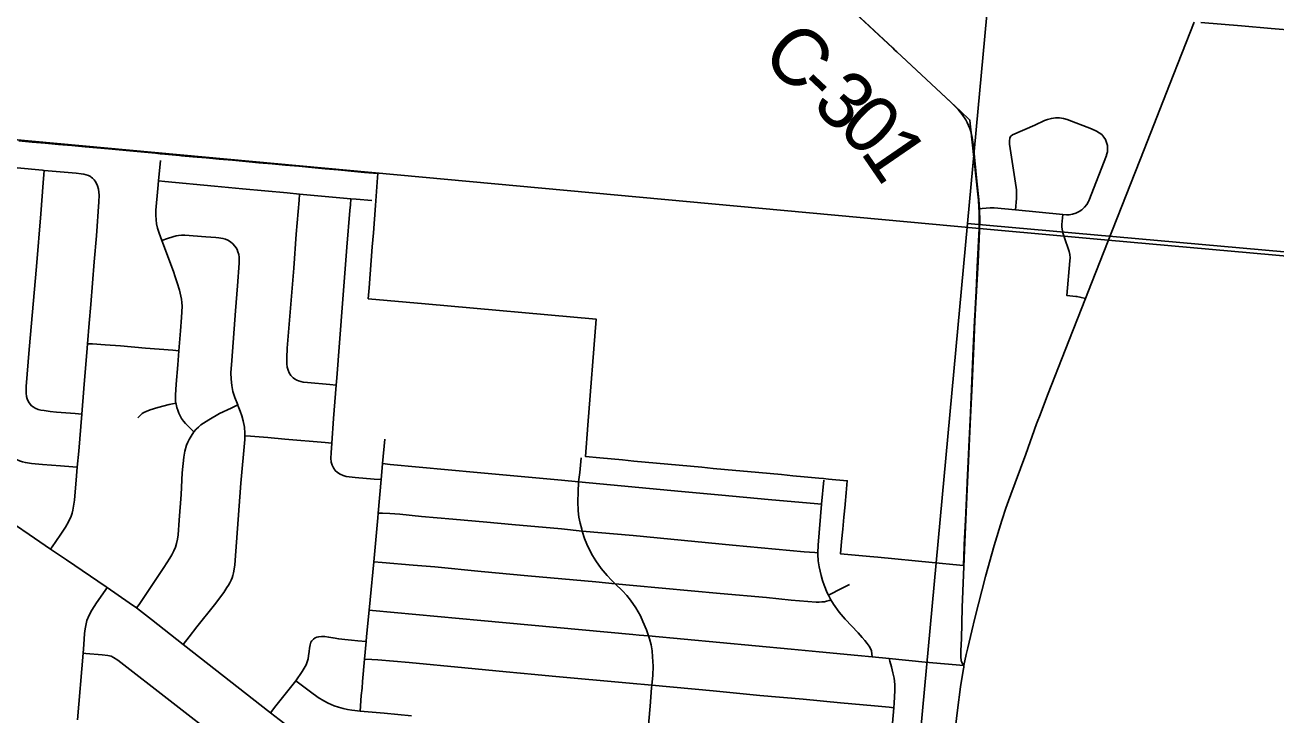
# Model space of a CAD drawing. Extents: x 0 to 1134, y 0 to 440.
# Drawn here: x 834.996 to 836.243, y 364.489 to 365.176 of the extents above; entities that cross this region are included whole.
import ezdxf

# ---------------------------------------------------------------- set-up
doc = ezdxf.new("R2010")
doc.units = 0
for name, color, linetype in [('GM_X_City_Street', 7, 'Continuous'), ('GM_X_Corporation', 7, 'Continuous'), ('GM_X_County_Road', 7, 'Continuous'), ('GM_X_County_Road_Text', 7, 'Continuous'), ('GM_X_Section', 7, 'Continuous'), ('GM_X_State_Route', 7, 'Continuous'), ('GM_X_Township', 7, 'Continuous'), ('GM_X_Township_Road', 7, 'Continuous'), ('GM_X_Unincorporated', 7, 'Continuous')]:
    doc.layers.add(name, color=color, linetype=linetype)

msp = doc.modelspace()

# ---------------------------------------------------------------- linework, layer by layer
at = {"layer": 'GM_X_City_Street'}
for points in [[(834.9536, 365.0365), (834.9603, 365.0361), (834.9634, 365.0359), (834.9883, 365.0336), (835.0133, 365.0314), (835.0149, 365.0312), (835.0469, 365.0284), (835.052, 365.0278), (835.0546, 365.0274), (835.057, 365.0268), (835.0591, 365.026), (835.0612, 365.0249), (835.0619, 365.0245)], [(835.0525, 364.7884), (835.046, 364.7889), (835.0272, 364.7904), (835.0209, 364.7911), (835.015, 364.7919), (835.0119, 364.7924), (835.0092, 364.793), (835.0062, 364.7942), (835.0041, 364.7955), (835.0026, 364.7967), (835.0012, 364.7981), (834.9995, 364.8007), (834.9981, 364.8035), (834.9975, 364.806), (834.997, 364.8092), (834.9971, 364.8157), (835.0002, 364.8526), (835.0075, 364.9355), (835.0117, 364.9878), (835.0139, 365.0186), (835.0146, 365.0272), (835.0149, 365.0312)], [(835.1644, 364.7708), (835.1605, 364.7744), (835.156, 364.779), (835.1539, 364.7813), (835.1521, 364.7839), (835.1506, 364.7865), (835.1493, 364.7893), (835.1482, 364.7922), (835.1473, 364.7951), (835.1465, 364.7981), (835.1464, 364.7992), (835.1461, 364.8012), (835.1459, 364.8043), (835.146, 364.8073), (835.1467, 364.8183), (835.1483, 364.8375), (835.1494, 364.8514), (835.1509, 364.8713), (835.152, 364.8845), (835.1525, 364.8959), (835.1523, 364.8997), (835.1519, 364.903), (835.1514, 364.906), (835.1499, 364.9118), (835.1477, 364.9191), (835.1457, 364.9251), (835.144, 364.9303), (835.1325, 364.9612), (835.1297, 364.9685), (835.128, 364.9737), (835.127, 364.9779), (835.1266, 364.982), (835.1264, 364.9864), (835.1265, 364.9914), (835.1284, 365.013), (835.129, 365.0206), (835.131, 365.0411)], [(835.0215, 364.6538), (835.0261, 364.6606), (835.0323, 364.6696), (835.0363, 364.6757), (835.0394, 364.6811), (835.0419, 364.6868), (835.0429, 364.6897), (835.0437, 364.6927), (835.0444, 364.6968), (835.0452, 364.7027), (835.0473, 364.7268), (835.0481, 364.7354), (835.0495, 364.7516), (835.0525, 364.7884), (835.0545, 364.8138), (835.0578, 364.8542), (835.0581, 364.8585), (835.0599, 364.879), (835.0615, 364.8976), (835.065, 364.9399), (835.0671, 364.9659), (835.0696, 364.9999), (835.0699, 365.0064), (835.0696, 365.0095), (835.0691, 365.0125), (835.0682, 365.0157), (835.0669, 365.0187), (835.0658, 365.0204), (835.0648, 365.0218), (835.0634, 365.0233), (835.0619, 365.0245)], [(835.129, 365.0206), (835.1353, 365.0201), (835.1848, 365.0155), (835.2127, 365.0129), (835.2574, 365.0087), (835.2696, 365.0076), (835.3208, 365.0029), (835.3261, 365.0024), (835.3416, 365.001)], [(835.3061, 364.8173), (835.2997, 364.8178), (835.2775, 364.8197), (835.2732, 364.8202), (835.2708, 364.8208), (835.2686, 364.8215), (835.2668, 364.8222), (835.2647, 364.8234), (835.2632, 364.8245), (835.2611, 364.8268), (835.2594, 364.8294), (835.2582, 364.8322), (835.2573, 364.8351), (835.2568, 364.8385), (835.2568, 364.841), (835.2568, 364.8444), (835.2574, 364.8539), (835.2594, 364.8779), (835.264, 364.9336), (835.2664, 364.9675), (835.2691, 365.0014), (835.2696, 365.0076)], [(835.351, 364.7231), (835.3439, 364.7237), (835.3252, 364.7251), (835.3191, 364.7258), (835.316, 364.7263), (835.313, 364.7271), (835.3102, 364.7284), (835.3076, 364.7301), (835.3053, 364.7323), (835.3034, 364.7347), (835.302, 364.7375), (835.3011, 364.7406), (835.3007, 364.7444), (835.301, 364.7498), (835.3017, 364.7594), (835.3035, 364.7839), (835.3061, 364.8173), (835.3067, 364.8246), (835.3125, 364.8986), (835.3167, 364.9545), (835.3199, 364.9913), (835.3203, 364.997), (835.3208, 365.0029)], [(835.1537, 364.559), (835.1596, 364.5666), (835.1672, 364.5764), (835.1847, 364.5982), (835.1941, 364.6106), (835.1973, 364.6156), (835.1989, 364.6179), (835.2002, 364.6203), (835.2015, 364.623), (835.2024, 364.6254), (835.2032, 364.6276), (835.2039, 364.6303), (835.2046, 364.634), (835.205, 364.6381), (835.2111, 364.7195), (835.2152, 364.7631), (835.2152, 364.7666), (835.2152, 364.7693), (835.2147, 364.7755), (835.2136, 364.7816), (835.2121, 364.7867), (835.2104, 364.7914), (835.2085, 364.7963), (835.208, 364.7975), (835.2051, 364.805), (835.2033, 364.8109), (835.202, 364.817), (835.2014, 364.8232), (835.2013, 364.8294), (835.202, 364.8418), (835.2058, 364.8914), (835.2077, 364.9163), (835.2093, 364.9388), (835.2095, 364.9419), (835.2095, 364.9447), (835.2092, 364.9472), (835.2082, 364.9501), (835.2073, 364.9523), (835.2063, 364.9541), (835.2052, 364.9556), (835.2033, 364.958), (835.2009, 364.96), (835.1983, 364.9616), (835.1958, 364.9626), (835.1932, 364.9633), (835.1893, 364.9639), (835.1861, 364.9642), (835.1761, 364.965), (835.1552, 364.9666), (835.1521, 364.9665), (835.149, 364.9662), (835.1465, 364.9658), (835.1432, 364.965), (835.138, 364.9633), (835.1325, 364.9612)], [(835.0581, 364.8585), (835.0633, 364.8582), (835.076, 364.8574), (835.0913, 364.8563), (835.116, 364.8542), (835.1433, 364.8519), (835.1494, 364.8514)], [(835.1071, 364.5953), (835.1098, 364.5986), (835.1216, 364.6165), (835.1343, 364.6354), (835.1403, 364.6447), (835.1423, 364.6481), (835.1443, 364.652), (835.1459, 364.6559), (835.1471, 364.6596), (835.1481, 364.6639), (835.1487, 364.6682), (835.1498, 364.6827), (835.1516, 364.7084), (835.1526, 364.73), (835.1543, 364.7454), (835.1554, 364.7515), (835.1571, 364.7575), (835.1583, 364.7604), (835.1597, 364.7631), (835.1616, 364.7664), (835.1644, 364.7708), (835.1666, 364.7733), (835.169, 364.7755), (835.1713, 364.7776), (835.1738, 364.7794), (835.1791, 364.7828), (835.19, 364.7888), (835.2016, 364.7944), (835.208, 364.7975)], [(835.1086, 364.7847), (835.1108, 364.787), (835.1128, 364.7888), (835.1144, 364.79), (835.1166, 364.7911), (835.1207, 364.7927), (835.1283, 364.795), (835.1398, 364.7978), (835.1464, 364.7992)], [(834.9302, 364.7811), (834.936, 364.7774), (834.9464, 364.7706), (834.9693, 364.7548), (834.9849, 364.7447), (834.9876, 364.7432), (834.9904, 364.7418), (834.9933, 364.7408), (834.9963, 364.74), (835.0024, 364.7391), (835.0133, 364.7381), (835.0312, 364.7367), (835.0435, 364.7357), (835.0481, 364.7354)], [(835.2152, 364.7666), (835.2208, 364.7663), (835.2381, 364.7649), (835.2549, 364.7635), (835.2951, 364.76), (835.3017, 364.7594)], [(835.3302, 364.4925), (835.3312, 364.508), (835.3319, 364.5155), (835.3325, 364.5221), (835.3345, 364.5443), (835.336, 364.5617), (835.3365, 364.5668), (835.3391, 364.593), (835.34, 364.6032), (835.3437, 364.6411), (835.3476, 364.685), (835.348, 364.6897), (835.351, 364.7231), (835.352, 364.7347), (835.3524, 364.739), (835.3546, 364.7635)], [(835.616, 364.4637), (835.619, 364.4973), (835.6206, 364.5158), (835.6209, 364.5183), (835.6218, 364.5281), (835.6221, 364.5373), (835.6216, 364.5465), (835.621, 364.5526), (835.62, 364.5586), (835.6184, 364.5646), (835.6175, 364.5674), (835.6155, 364.5733), (835.612, 364.5819), (835.6094, 364.5874), (835.6048, 364.5954), (835.5997, 364.603), (835.5958, 364.6078), (835.5917, 364.6123), (835.5844, 364.6193), (835.5805, 364.623), (835.5762, 364.6275), (835.5702, 364.6347), (835.5649, 364.6423), (835.5616, 364.6476), (835.5586, 364.6531), (835.5559, 364.6588), (835.5537, 364.6646), (835.5515, 364.6718), (835.5509, 364.6736), (835.5494, 364.6796), (835.5482, 364.6858), (835.5475, 364.692), (835.5471, 364.7013), (835.5474, 364.7107), (835.5478, 364.721), (835.5489, 364.7302), (835.5505, 364.7447)], [(835.3524, 364.739), (835.3601, 364.7383), (835.4466, 364.7303), (835.5051, 364.725), (835.5309, 364.7226), (835.5478, 364.721), (835.6503, 364.7114), (835.6905, 364.7076), (835.7368, 364.7033), (835.7864, 364.6991), (835.7901, 364.6988)], [(835.8405, 364.5465), (835.8401, 364.5495), (835.8397, 364.5524), (835.8389, 364.5547), (835.8375, 364.5572), (835.8356, 364.5598), (835.833, 364.5627), (835.8304, 364.5658), (835.8264, 364.5705), (835.8136, 364.5841), (835.8076, 364.5912), (835.802, 364.599), (835.7994, 364.6034), (835.7986, 364.6048), (835.7969, 364.6079), (835.7956, 364.6102), (835.7925, 364.6181), (835.7909, 364.6227), (835.7896, 364.6275), (835.7877, 364.6361), (835.7867, 364.6422), (835.7862, 364.6484), (835.7863, 364.6501), (835.7866, 364.6577), (835.7901, 364.6988), (835.7922, 364.7226)], [(835.348, 364.6897), (835.3522, 364.6897), (835.3596, 364.6894), (835.3696, 364.6886), (835.3913, 364.6863), (835.4223, 364.6837), (835.4564, 364.6806), (835.4812, 364.6783), (835.5308, 364.6739), (835.5515, 364.6718), (835.6021, 364.6673), (835.7013, 364.6578), (835.7726, 364.6513), (835.7832, 364.6504), (835.7863, 364.6501)], [(835.3437, 364.6411), (835.3519, 364.6406), (835.3828, 364.638), (835.4044, 364.6361), (835.4508, 364.6315), (835.4971, 364.6273), (835.5651, 364.6211), (835.5844, 364.6193), (835.6022, 364.6176), (835.6888, 364.6098), (835.7351, 364.6055), (835.7598, 364.6031), (835.7846, 364.6011), (835.7876, 364.601), (835.7903, 364.6012), (835.7929, 364.6015), (835.7951, 364.602), (835.7975, 364.6028), (835.7994, 364.6034)], [(835.7969, 364.6079), (835.8003, 364.6097), (835.8071, 364.6133), (835.818, 364.6186)], [(835.0484, 364.4838), (835.0539, 364.5502), (835.0546, 364.5589), (835.0554, 364.5697), (835.0559, 364.5744), (835.0565, 364.5778), (835.0577, 364.5829), (835.06, 364.5882), (835.0626, 364.593), (835.0671, 364.6002), (835.0758, 364.6125), (835.0779, 364.6155)], [(835.3391, 364.593), (835.3425, 364.5927), (835.4505, 364.5829), (835.602, 364.5688), (835.6082, 364.5682), (835.6175, 364.5674), (835.7598, 364.5542), (835.7875, 364.5516), (835.8263, 364.5479), (835.8405, 364.5465), (835.8574, 364.5449), (835.8933, 364.5414)], [(835.2853, 364.5656), (835.2836, 364.5643), (835.282, 364.5626), (835.281, 364.561), (835.2801, 364.5585), (835.2795, 364.5552), (835.2791, 364.5519), (835.2786, 364.5474), (835.2781, 364.5447), (835.2773, 364.5416), (835.2762, 364.5387), (835.2744, 364.5352), (835.2723, 364.5318), (835.2658, 364.5228)], [(835.2853, 364.5656), (835.287, 364.5662), (835.2887, 364.5666), (835.2916, 364.5669), (835.295, 364.5668), (835.2986, 364.5662), (835.303, 364.5654), (835.3087, 364.5644), (835.3148, 364.5637), (835.3214, 364.563), (835.3278, 364.5625), (835.336, 364.5617)], [(835.1927, 364.4621), (835.0884, 364.5431), (835.0843, 364.5459), (835.0817, 364.5471), (835.0784, 364.5479), (835.073, 364.5487), (835.0567, 364.55), (835.0539, 364.5502)], [(835.3345, 364.5443), (835.3416, 364.5439), (835.3478, 364.5435), (835.3788, 364.5408), (835.4345, 364.5357), (835.4755, 364.5317), (835.5043, 364.529), (835.5215, 364.5274), (835.5984, 364.5203), (835.6209, 364.5183), (835.682, 364.5126), (835.7284, 364.5081), (835.7718, 364.5045), (835.8089, 364.5008), (835.8429, 364.4977), (835.8574, 364.4964), (835.8621, 364.4959)], [(835.8583, 364.454), (835.8621, 364.4959), (835.8625, 364.5005), (835.8632, 364.5129), (835.8631, 364.5191), (835.8624, 364.5252), (835.8612, 364.5307), (835.8597, 364.5366), (835.8581, 364.5421), (835.8574, 364.5449)], [(835.2658, 364.5228), (835.2461, 364.4977), (835.2407, 364.4908)], [(835.2658, 364.5228), (835.2806, 364.5118), (835.2883, 364.5062), (835.2937, 364.5028), (835.2982, 364.5003), (835.3043, 364.4977), (835.3084, 364.4964), (835.313, 364.4951), (835.3176, 364.4941), (835.3219, 364.4934), (835.3246, 364.4931), (835.3274, 364.4928), (835.3302, 364.4925)], [(835.3302, 364.4925), (835.3539, 364.4903), (835.3814, 364.4877)]]:
    msp.add_lwpolyline(points, dxfattribs=at)
at = {"layer": 'GM_X_Corporation'}
for points in [[(834.9898, 365.0606), (835.003, 365.0594), (835.0162, 365.0582), (835.0294, 365.057), (835.0426, 365.0558), (835.0558, 365.0546), (835.0791, 365.0525), (835.1006, 365.0505), (835.1261, 365.0482), (835.1308, 365.0478), (835.1355, 365.0473), (835.15, 365.046), (835.152, 365.0458), (835.1632, 365.0448), (835.1764, 365.0436), (835.1896, 365.0424), (835.2028, 365.0412), (835.216, 365.04), (835.2292, 365.0388), (835.2424, 365.0376), (835.2556, 365.0364), (835.2688, 365.0352), (835.282, 365.0339), (835.2952, 365.0327), (835.308, 365.0316), (835.3212, 365.0304), (835.3344, 365.0292), (835.3478, 365.0279), (835.3475, 365.0241), (835.3461, 365.0056), (835.3457, 365.0009), (835.3453, 364.9961), (835.3443, 364.9825), (835.3432, 364.9688), (835.3421, 364.9551), (835.3411, 364.9414), (835.34, 364.9278), (835.3389, 364.9141), (835.3381, 364.9033), (835.3949, 364.8982), (835.5654, 364.8829), (835.5571, 364.7773), (835.5548, 364.7461), (835.569, 364.7448), (835.5803, 364.7437), (835.5916, 364.7427), (835.6029, 364.7416), (835.6142, 364.7406), (835.6255, 364.7396), (835.6369, 364.7385), (835.6482, 364.7375), (835.6595, 364.7364), (835.6708, 364.7354), (835.6821, 364.7343), (835.6934, 364.7333), (835.7047, 364.7322), (835.7161, 364.7312), (835.7274, 364.7302), (835.7387, 364.7291), (835.75, 364.7281), (835.7613, 364.727), (835.7726, 364.726), (835.7874, 364.7246), (835.7921, 364.7242), (835.7968, 364.7237), (835.8156, 364.722), (835.8145, 364.7099), (835.8135, 364.6988), (835.8134, 364.6979), (835.8122, 364.6858), (835.8111, 364.6737), (835.8099, 364.6614), (835.8088, 364.6493), (835.8381, 364.6465), (835.8462, 364.6457), (835.9003, 364.6405), (835.9278, 364.6379), (835.9315, 364.6375), (835.9322, 364.6566), (835.9323, 364.6581), (835.9338, 364.6893), (835.9338, 364.6905), (835.9349, 364.7123), (835.9356, 364.7278), (835.9362, 364.7413), (835.9372, 364.7628), (835.9384, 364.7892), (835.9413, 364.854), (835.9426, 364.8816), (835.9431, 364.8918), (835.9432, 364.8933), (835.944, 364.9112), (835.944, 364.9112), (835.9451, 364.935), (835.947, 364.9732), (835.9471, 364.9776), (835.9471, 364.9778), (835.9471, 364.978), (835.9471, 364.9782), (835.9471, 364.9784), (835.9471, 364.9786), (835.9471, 364.9787), (835.9471, 364.9789), (835.9471, 364.9791), (835.9471, 364.9793), (835.9471, 364.9795), (835.9471, 364.9797), (835.9471, 364.9799), (835.9471, 364.98), (835.9471, 364.9802), (835.9471, 364.9804), (835.9471, 364.9806), (835.9471, 364.9808), (835.9471, 364.981), (835.9471, 364.9812), (835.9471, 364.9813), (835.9471, 364.9815), (835.9471, 364.9817), (835.9471, 364.9819), (835.9471, 364.9821), (835.9471, 364.9823), (835.9471, 364.9824), (835.9471, 364.9826), (835.9471, 364.9828), (835.9471, 364.983), (835.9471, 364.9832), (835.9471, 364.9834), (835.9471, 364.9836), (835.9471, 364.9837), (835.9471, 364.9839), (835.9471, 364.9841), (835.9471, 364.9843), (835.9471, 364.9845), (835.9471, 364.9847), (835.9471, 364.9849), (835.9471, 364.985), (835.9471, 364.9852), (835.9471, 364.9854), (835.9471, 364.9856), (835.9471, 364.9858), (835.9471, 364.986), (835.9471, 364.9862), (835.9471, 364.9863), (835.9471, 364.9865), (835.9471, 364.9867), (835.9471, 364.9869), (835.9471, 364.9871), (835.9471, 364.9873), (835.9471, 364.9875), (835.9471, 364.9876), (835.9471, 364.9878), (835.9471, 364.988), (835.9471, 364.9882), (835.9471, 364.9884), (835.9471, 364.9886), (835.9471, 364.9888), (835.9471, 364.9889), (835.947, 364.9891), (835.947, 364.9893), (835.947, 364.9895), (835.947, 364.9897), (835.947, 364.9899), (835.947, 364.99), (835.947, 364.9902), (835.947, 364.9904), (835.947, 364.9906), (835.947, 364.9908), (835.947, 364.991), (835.947, 364.9912), (835.947, 364.9913), (835.947, 364.9915), (835.947, 364.9917), (835.947, 364.9919), (835.947, 364.9921), (835.9469, 364.9923), (835.9469, 364.9925), (835.9469, 364.9926), (835.9469, 364.9928), (835.9469, 364.993), (835.9469, 364.9932), (835.9469, 364.9934), (835.9469, 364.9936), (835.9469, 364.9938), (835.9469, 364.9939), (835.9469, 364.9941), (835.9469, 364.9943), (835.9468, 364.9945), (835.9468, 364.9947), (835.9468, 364.9949), (835.9468, 364.9951), (835.9468, 364.9952), (835.9468, 364.9954), (835.9468, 364.9956), (835.9468, 364.9958), (835.9468, 364.996), (835.9468, 364.9962), (835.9467, 364.9963), (835.9467, 364.9965), (835.9467, 364.9967), (835.9467, 364.9969), (835.9467, 364.9971), (835.9467, 364.9973), (835.9467, 364.9975), (835.9467, 364.9976), (835.9467, 364.9978), (835.9466, 364.998), (835.9466, 364.9982), (835.9466, 364.9984), (835.9466, 364.9986), (835.9466, 364.9988), (835.9466, 364.9989), (835.9466, 364.9991), (835.9466, 364.9993), (835.9465, 364.9995), (835.9465, 364.9997), (835.9465, 364.9999), (835.9465, 365), (835.9465, 365.0002), (835.9465, 365.0004), (835.9465, 365.0006), (835.9464, 365.0008), (835.9464, 365.001), (835.9464, 365.0012), (835.9464, 365.0013), (835.9464, 365.0015), (835.9464, 365.0017), (835.9464, 365.0019), (835.9463, 365.0021), (835.9463, 365.0023), (835.9463, 365.0024), (835.9463, 365.0026), (835.9463, 365.0028), (835.9463, 365.003), (835.9462, 365.0032), (835.9462, 365.0034), (835.9462, 365.0036), (835.9462, 365.0037), (835.9462, 365.0039), (835.9462, 365.0041), (835.9461, 365.0043), (835.9461, 365.0045), (835.9461, 365.0047), (835.9461, 365.0048), (835.9461, 365.005), (835.9461, 365.0052), (835.946, 365.0054), (835.946, 365.0056), (835.946, 365.0058), (835.946, 365.0059), (835.946, 365.0061), (835.9459, 365.0062), (835.9459, 365.0063), (835.9459, 365.0065), (835.9459, 365.0067), (835.9459, 365.0068), (835.9459, 365.0069), (835.9459, 365.007), (835.9459, 365.0072), (835.9458, 365.0074), (835.9458, 365.0075), (835.9386, 365.0747), (835.9379, 365.0813), (835.9359, 365.0831), (835.9302, 365.0884), (835.9285, 365.09), (835.8895, 365.1264), (835.865, 365.1493), (835.8632, 365.151), (835.8609, 365.1531), (835.8245, 365.1872)], [(836.168, 365.1785), (836.2086, 365.1751), (836.2381, 365.1726), (836.3111, 365.1664)]]:
    msp.add_lwpolyline(points, dxfattribs=at)
at = {"layer": 'GM_X_County_Road'}
for points in [[(835.9473, 364.9929), (835.9467, 365.002), (835.9449, 365.0205), (835.9414, 365.0545), (835.9401, 365.0638), (835.9387, 365.0699), (835.9377, 365.0729), (835.9365, 365.0759), (835.9352, 365.0787), (835.9337, 365.0815), (835.9302, 365.0868), (835.9263, 365.0917), (835.9197, 365.0984), (835.8947, 365.1217), (835.8743, 365.1407), (835.8515, 365.1618), (835.8039, 365.2064), (835.7697, 365.238), (835.747, 365.2592), (835.7267, 365.2784), (835.7041, 365.2996), (835.682, 365.3204)], [(835.932, 364.5378), (835.9302, 364.5402), (835.9297, 364.5411), (835.9294, 364.5418), (835.9292, 364.5426), (835.9291, 364.5436), (835.9289, 364.5459), (835.9289, 364.5527), (835.9294, 364.5646), (835.9301, 364.5956), (835.9328, 364.6608), (835.9352, 364.7135), (835.9365, 364.7414), (835.9383, 364.7786), (835.94, 364.8189), (835.9418, 364.8561), (835.9428, 364.8809), (835.9437, 364.8995), (835.946, 364.9398), (835.9475, 364.9708), (835.9476, 364.9727), (835.9477, 364.9802), (835.9473, 364.9929)]]:
    msp.add_lwpolyline(points, dxfattribs=at)
at = {"layer": 'GM_X_Section'}
for points in [[(836.0273, 365.9691), (837.0319, 365.8778), (836.9458, 364.8879), (835.9355, 364.9781)], [(835.9355, 364.9781), (836.9458, 364.8879), (836.8475, 363.8721), (835.8418, 363.9641)]]:
    msp.add_lwpolyline(points, close=True, dxfattribs=at)
at = {"layer": 'GM_X_State_Route'}
for points in [[(836.0758, 364.961), (836.1116, 365.052), (836.1368, 365.1165), (836.1614, 365.1789)], [(836.0071, 364.7859), (836.0159, 364.8088), (836.0328, 364.8522), (836.0531, 364.9034), (836.0592, 364.9187), (836.0758, 364.961)], [(835.9764, 364.7019), (835.9787, 364.7083), (835.983, 364.72), (835.9935, 364.7486), (836.0044, 364.7788), (836.0057, 364.7821), (836.0071, 364.7859)], [(835.97, 364.6835), (835.9737, 364.6945), (835.9764, 364.7019)], [(835.932, 364.5378), (835.9343, 364.5489), (835.9357, 364.5554), (835.9398, 364.5723), (835.9429, 364.5851), (835.9535, 364.6266), (835.9621, 364.6574), (835.9697, 364.6824), (835.97, 364.6835)], [(835.9222, 364.4659), (835.9254, 364.4934), (835.9284, 364.5166), (835.9301, 364.5271), (835.9314, 364.5346), (835.9317, 364.5362), (835.932, 364.5378)]]:
    msp.add_lwpolyline(points, dxfattribs=at)
at = {"layer": 'GM_X_Township'}
msp.add_lwpolyline([(834.9555, 365.0647), (835.9473, 364.9732), (836.0317, 364.9655), (836.0756, 364.9615), (837.3093, 364.8515), (837.4445, 364.8393), (837.9386, 364.7921), (838.074, 364.7826), (838.4147, 364.746), (839.7495, 364.6071)], dxfattribs=at)
at = {"layer": 'GM_X_Township_Road'}
for p, q in [((835.9833, 364.9919), (836.0306, 364.9872)), ((835.1537, 364.559), (835.2407, 364.4908)), ((835.8933, 364.5414), (835.932, 364.5378))]:
    msp.add_line(p, q, dxfattribs=at)
for points in [[(835.9833, 364.9919), (835.9843, 365.003), (835.9844, 365.0067), (835.9842, 365.0119), (835.9839, 365.0141), (835.9773, 365.0573), (835.9772, 365.0582), (835.9772, 365.0609), (835.9776, 365.063), (835.9778, 365.0636), (835.9788, 365.0652), (835.9802, 365.0665), (836.0025, 365.0761), (836.0123, 365.0808), (836.0154, 365.082), (836.0192, 365.083), (836.0232, 365.0835), (836.0271, 365.0835), (836.0311, 365.083), (836.0348, 365.082), (836.0592, 365.0724)], [(836.0306, 364.9872), (836.0343, 364.987), (836.0368, 364.987), (836.0403, 364.9875), (836.0436, 364.9886), (836.0467, 364.9901), (836.0496, 364.992), (836.0522, 364.9944), (836.0543, 364.9971), (836.0561, 365.0001), (836.0564, 365.0008), (836.074, 365.046), (836.0742, 365.0467), (836.075, 365.0497), (836.0752, 365.0528), (836.075, 365.0559), (836.0742, 365.0589), (836.073, 365.0618), (836.0713, 365.0644), (836.0693, 365.0668), (836.0669, 365.0687), (836.0642, 365.0703), (836.0592, 365.0724)], [(835.9473, 364.9929), (835.95, 364.9932), (835.9581, 364.9938), (835.9622, 364.994), (835.9833, 364.9919)], [(836.0531, 364.9034), (836.0476, 364.905), (836.0446, 364.9056), (836.0436, 364.9056), (836.0346, 364.9065), (836.0374, 364.9411), (836.0377, 364.944), (836.0374, 364.9472), (836.0367, 364.9502), (836.0319, 364.965), (836.0306, 364.9691), (836.0301, 364.971), (836.0296, 364.9745), (836.0296, 364.9773), (836.0306, 364.9872)], [(834.9023, 364.7307), (834.9247, 364.7181), (834.938, 364.71), (834.959, 364.6962), (835.0001, 364.6685), (835.0215, 364.6538)], [(835.0215, 364.6538), (835.0372, 364.6433), (835.0768, 364.6162), (835.0779, 364.6155)], [(835.0779, 364.6155), (835.0998, 364.6003), (835.1071, 364.5953)], [(835.1071, 364.5953), (835.1222, 364.5836), (835.1537, 364.559)], [(835.2407, 364.4908), (835.2492, 364.4841), (835.2788, 364.4616), (835.2915, 364.4528), (835.3149, 364.4377), (835.3321, 364.4269)]]:
    msp.add_lwpolyline(points, dxfattribs=at)
at = {"layer": 'GM_X_Unincorporated'}
msp.add_lwpolyline([(841.3922, 369.3181), (835.2574, 369.3181), (835.2208, 368.8787), (835.1738, 368.323), (835.1229, 367.735), (835.0626, 367.0305), (835.0377, 366.7503), (835.0373, 366.7416), (834.973, 366.0452), (834.8862, 365.0705), (834.9555, 365.0647), (835.9473, 364.9732), (836.0317, 364.9655), (836.0756, 364.9615), (837.3093, 364.8515), (837.4445, 364.8393), (837.9386, 364.7921), (838.074, 364.7826), (838.4147, 364.746), (839.7495, 364.6071)], dxfattribs=at)

# ---------------------------------------------------------------- texts
at = {"layer": 'GM_X_County_Road_Text'}
for s, rotation, p in [('C', 316.6934, (835.728, 365.143)), ('-', 316.6892, (835.762, 365.111)), ('3', 316.7111, (835.779, 365.0949)), ('0', 316.7597, (835.8045, 365.0709)), ('1', 304.4796, (835.8279, 365.0494))]:
    msp.add_text(s, height=0.0568, rotation=rotation, dxfattribs=at).set_placement(p)

doc.saveas('drawing.dxf')
